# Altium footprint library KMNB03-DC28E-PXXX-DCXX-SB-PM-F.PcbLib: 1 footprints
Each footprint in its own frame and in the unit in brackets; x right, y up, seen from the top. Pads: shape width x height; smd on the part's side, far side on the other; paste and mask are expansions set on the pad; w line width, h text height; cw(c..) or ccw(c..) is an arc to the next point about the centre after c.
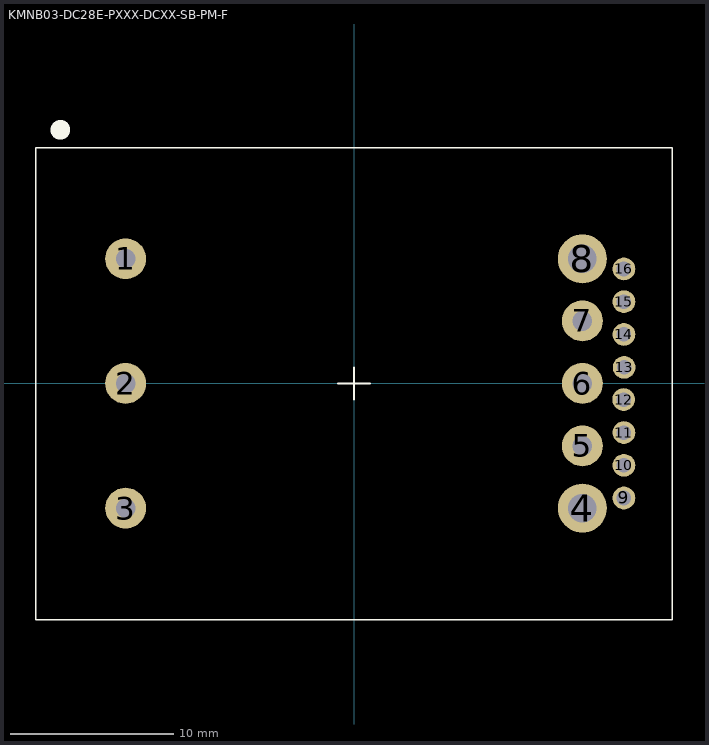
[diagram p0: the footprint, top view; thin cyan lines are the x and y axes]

## KMNB03-DC28E-PXXX-DCXX-SB-PM-F [mm] "KMNB03-DC28E-PXXX-DCXX-SB-PM-F"
height 12.7
pads (16):
  round 2.5 hole 1.2: 1(-13.96,7.62) 2(-13.96,0) 3(-13.96,-7.62) 5(13.96,-3.82) 6(13.96,0) 7(13.96,3.82)
  round 3 hole 1.75: 4(13.96,-7.62) 8(13.96,7.62)
  round 1.39 hole 0.89: 9(16.5,-7.001) 10(16.5,-5.002) 11(16.5,-3.002) 12(16.483,-0.985) 13(16.513,0.985) 14(16.5,2.998) 15(16.5,4.998) 16(16.5,6.998)
Top Overlay:
  circle w1: c-17.95,15.505 r0.1
  lines w0.1: -1,0 0,0 ; 0,-1 0,0 ; 0,1 0,0 ; 1,0 0,0 ; -19.45,-14.45 -19.45,14.4 19.45,14.4 19.45,-14.45 -19.45,-14.45
Bottom Overlay:
  circle w1: c-17.95,12.495 r0.1
  text "-VOUT" at 17.9,-9.883 h0.7
  text "-SENSE" at 17.9,-5.983 h0.7
  text "TRIM" at 17.9,-1.225 h0.7
  text "+SENSE" at 17.9,2.017 h0.7
  text "+VOUT" at 17.9,6.617 h0.7
  text "+VIN" at -18.6,6.376 h0.7
  text "ON/OFF" at -18.6,-1.965 h0.7
  text "-VIN" at -18.6,-8.849 h0.7
3D body "KMNB03-F.STEP": height 13.01, standoff -4.59, extent -19.199,-18.852 19.201,19.248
